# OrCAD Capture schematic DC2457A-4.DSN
size Custom; title: 60V LOW EMI SYNCHRONOUS 4-SWITCH; rev: 4; note: DC2457A
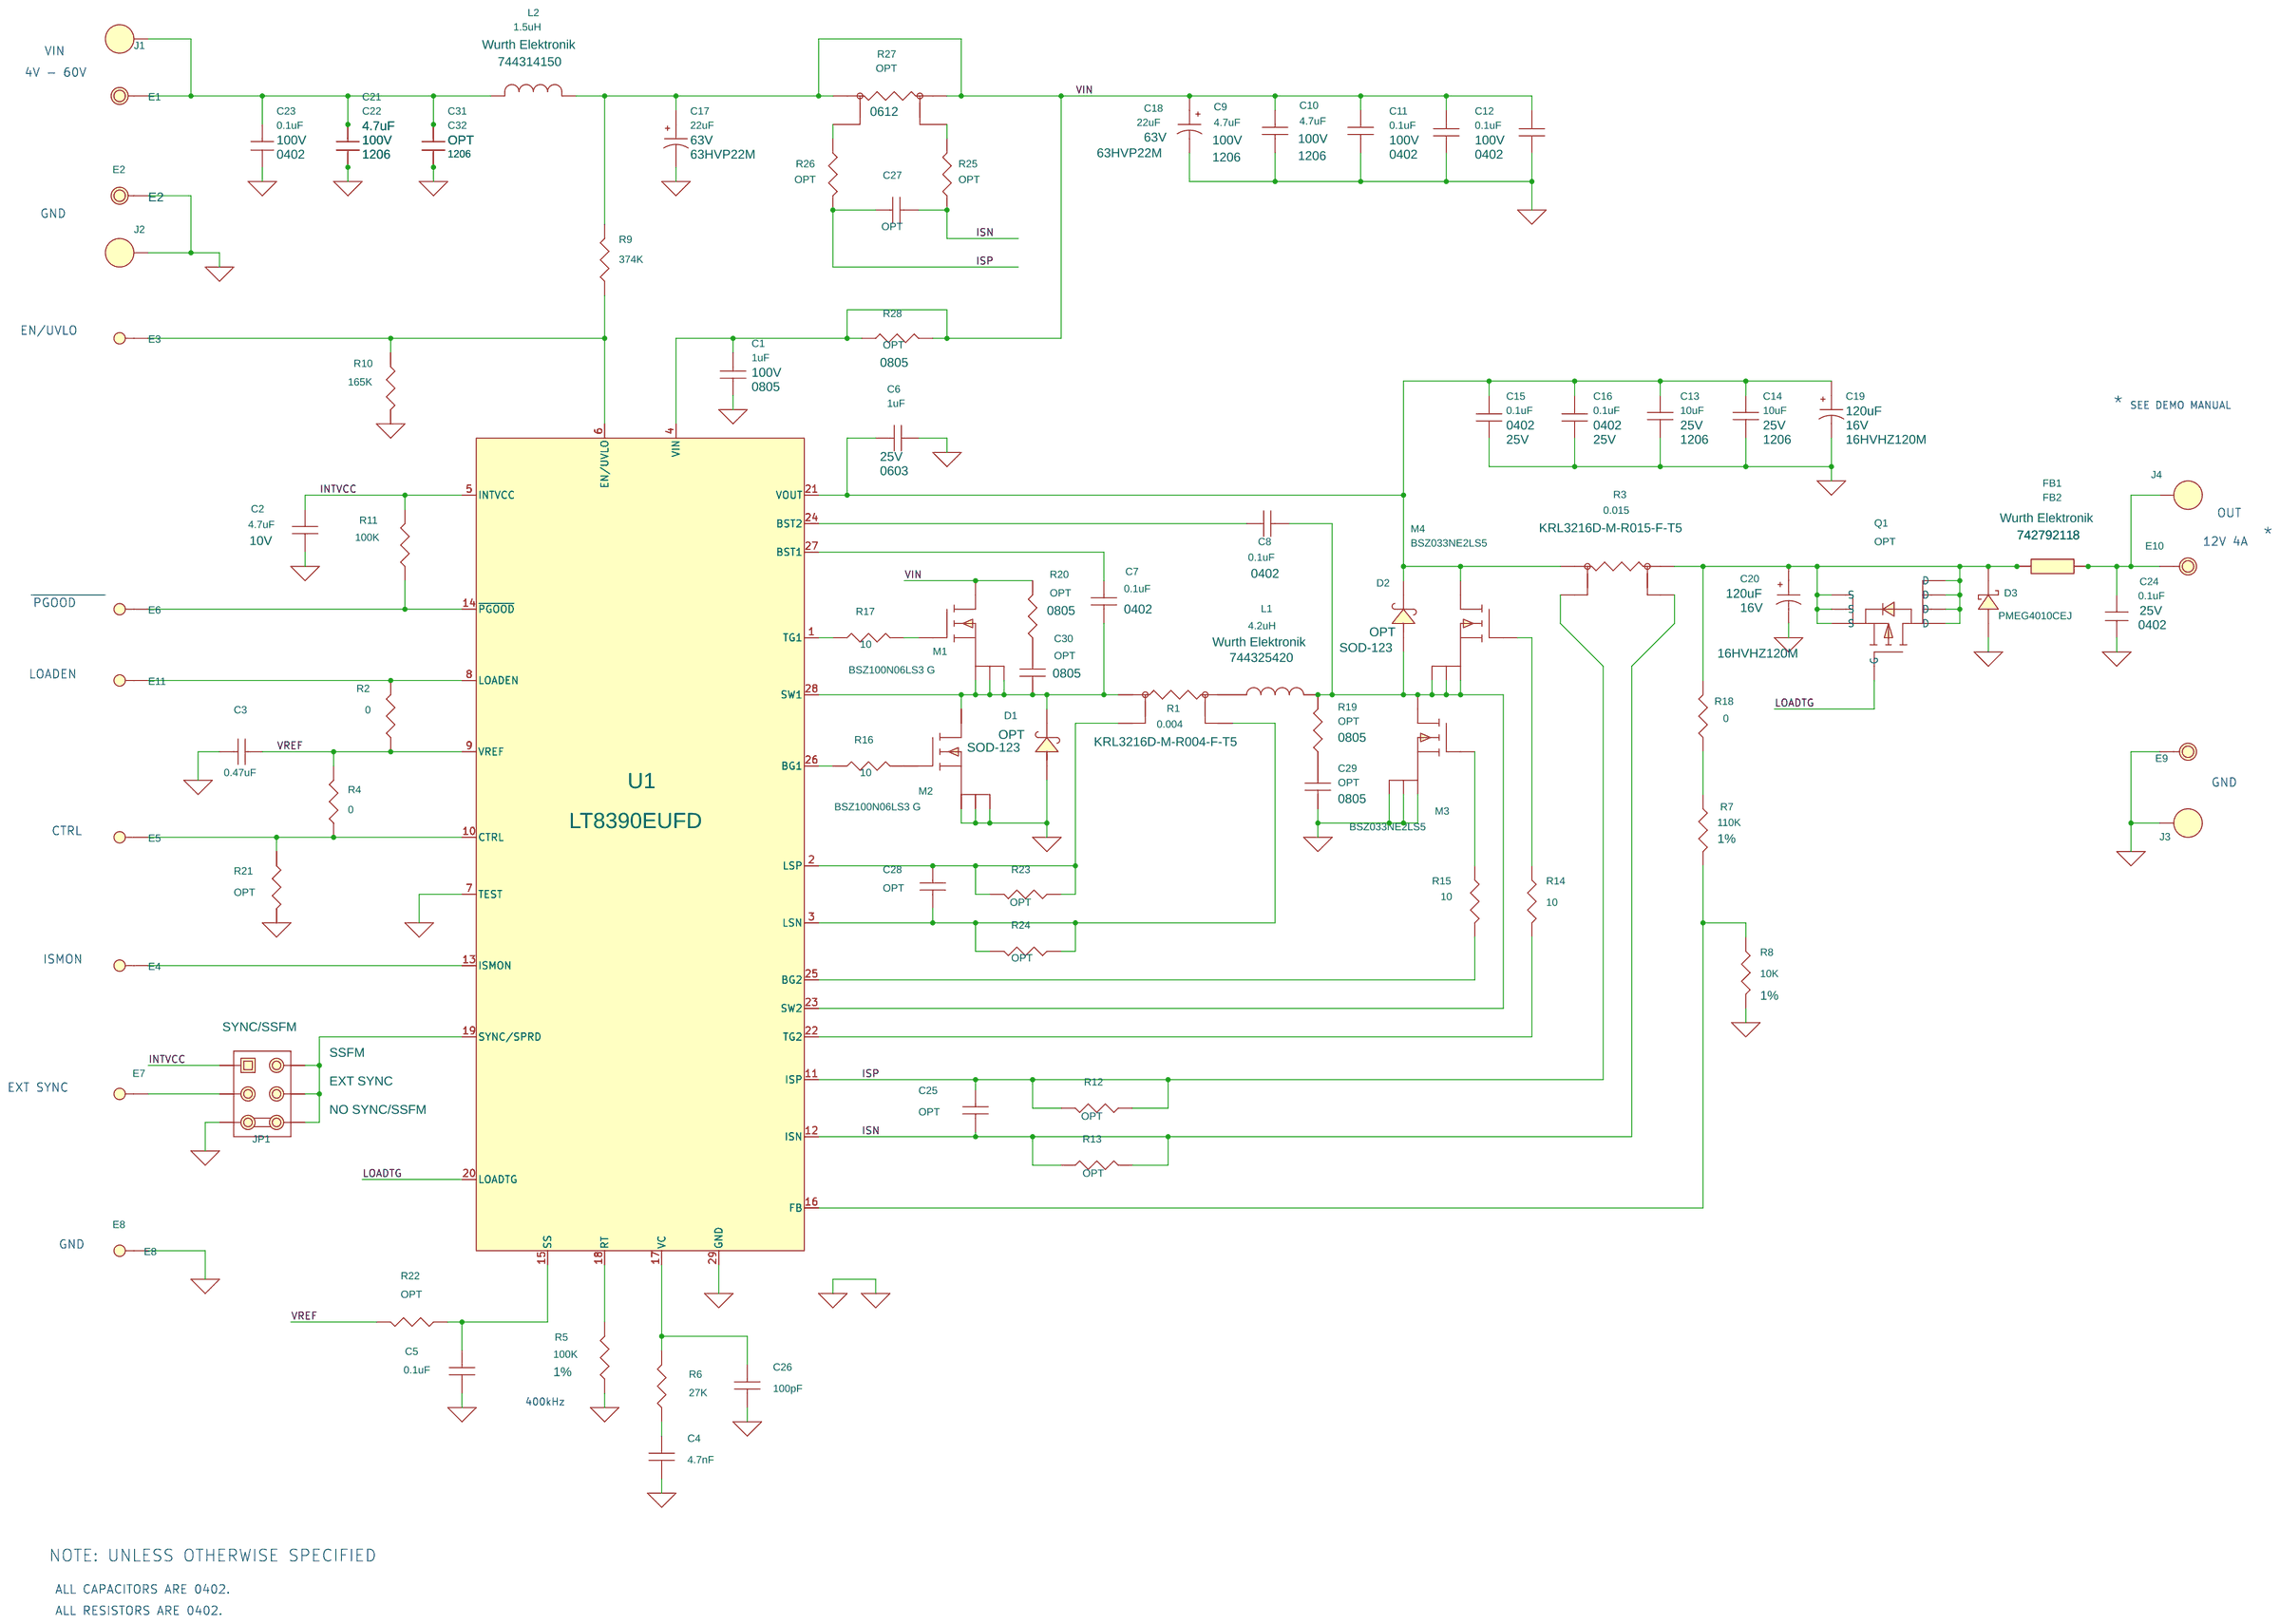
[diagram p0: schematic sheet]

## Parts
C1  1uF  [0805]
C2  4.7uF  [0402]
C3  0.47uF  [0402]
C4  4.7nF  [0402]
C5  0.1uF  [0402]
C6  1uF  [0603]
C7  0.1uF  [0402]
C8  0.1uF  [0402]
C9  4.7uF  [1206]
C10  4.7uF  [1206]
C11  0.1uF  [0402]
C12  0.1uF  [0402]
C13  10uF  [1206]
C14  10uF  [1206]
C15  0.1uF  [0402]
C16  0.1uF  [0402]
C17  22uF  [CAP-CE-8x10.2]
C18  22uF  [CAP-CE-8x10.2]
C19  120uF  [CAP-CE-BS-6.3X7.7]
C20  120uF  [CAP-CE-BS-6.3X7.7]
C21  4.7uF  [1206]
C22  4.7uF  [1206]
C23  0.1uF  [0402]
C24  0.1uF  [0402]
C25  OPT  [0402]
C26  100pF  [0402]
C27  OPT  [0402]
C28  OPT  [0402]
C29  OPT  [0805]
C30  OPT  [0805]
C31  OPT  [1206]
C32  OPT  [1206]
D1  OPT  [SOD-123]
D2  OPT  [SOD-123]
D3  PMEG4010CEJ  [SOD-323F]
E1  Testpoint  [MM/2501]
E2  Testpoint  [MM/2501]
E3  Testpoint  [MM/2308]
E4  Testpoint  [MM/2308]
E5  Testpoint  [MM/2308]
E6  Testpoint  [MM/2308]
E7  Testpoint  [MM/2308]
E8  Testpoint  [MM/2308]
E9  Testpoint  [MM/2501]
E10  Testpoint  [MM/2501]
E11  Testpoint  [MM/2308]
FB1  742792118  [1206]
FB2  742792118  [1206]
J1  BANANA-JACK  [KEY-575-4]
J2  BANANA-JACK  [KEY-575-4]
J3  BANANA-JACK  [KEY-575-4]
J4  BANANA-JACK  [KEY-575-4]
JP1  3 Pins 2mm Ctrs.  [JP3X2/079]
L1  4.2uH  [IND-744325]
L2  1.5uH  [IND-744314]
M1  BSZ100N06LS3 G  [POWERPAK-1212-8-S-5P]
M2  BSZ100N06LS3 G  [POWERPAK-1212-8-S-5P]
M3  BSZ033NE2LS5  [POWERPAK-1212-8-S-5P]
M4  BSZ033NE2LS5  [POWERPAK-1212-8-S-5P]
Q1  OPT  [POWERPAK-1212-8-S]
R1  0.004  [0612]
R2  0  [0402]
R3  0.015  [0612]
R4  0  [0402]
R5  100K  [0402]
R6  27K  [0402]
R7  110K  [0402]
R8  10K  [0402]
R9  374K  [0402]
R10  165K  [0402]
R11  100K  [0402]
R12  OPT  [0402]
R13  OPT  [0402]
R14  10  [0402]
R15  10  [0402]
R16  10  [0402]
R17  10  [0402]
R18  0  [0402]
R19  OPT  [0805]
R20  OPT  [0805]
R21  OPT  [0402]
R22  OPT  [0402]
R23  OPT  [0402]
R24  OPT  [0402]
R25  OPT  [0402]
R26  OPT  [0402]
R27  OPT  [0612]
R28  OPT  [0805]
U1  LT8390EUFD  [QFN-28-4X5]
XJP1  2mm Ctrs.

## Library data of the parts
C1 = CAP_NP: 1st Part Field: V; 4th Part Field: MF; 7th Part Field: CAP.,; Voltage: 100V
C2 = CAP_NP: 1st Part Field: V; 4th Part Field: MF; 7th Part Field: CAP.,; Voltage: 10V
C3-C5 C7 C8 C25-C29 = CAP_NP: 1st Part Field: V; 4th Part Field: MF; 7th Part Field: CAP.,; Voltage: 6.3V
C6 = CAP_NP: 1st Part Field: V; 4th Part Field: MF; 7th Part Field: CAP.,; Voltage: 25V
C9-C12 = CAP_NP: 1st Part Field: 100V; 4th Part Field: MF; 7th Part Field: CAP.,; Voltage: 100V
C13-C16 = CAP_NP: 1st Part Field: 25V; 4th Part Field: MF; 7th Part Field: CAP.,; Voltage: 25V
C17 C18 = 16TQC47M: 1st Part Field: 63V; 2nd Part Field: 20%; 4th Part Field: SUN ELEC.; 5th Part Field: 63HVP22M; 7th Part Field: CAP.,
C19 C20 = 16TQC47M: 1st Part Field: 16V; 2nd Part Field: 20%; 4th Part Field: SUN ELEC.; 5th Part Field: 16HVHZ120M; 7th Part Field: CAP.,
C21-C23 = CAP0603: 1ST PART FIELD: 100V; Voltage: 100V
C24 = CAP0603: 1ST PART FIELD: 25V; Voltage: 25V
C30 = CAP_NP: 1st Part Field: V; 4th Part Field: MF / MF / MF; 7th Part Field: CAP.,; Voltage: 6.3V
C31 = CAP0603: 1ST PART FIELD: V; 2ND PART FIELD: % 0603; 3RD PART FIELD: TYPE; 5TH PART FIELD: 0603
C32 = CAP0603
D1 D2 = DIODE_4
D3 = BAT54WS: 1ST PART FIELD: DIODE SCHOTTKY; 4TH PART FIELD: NXP Semiconductors; 5TH PART FIELD: PMEG6010CEJ,115; 7TH PART FIELD: DIODE SCHOTTKY,
E1 E2 E9 E10 = MillMax-2501-2_2: V: GND
E3-E5 E7 E8 E11 = MillMax-2501-2_3: V: GND
E6 = MillMax-2501-2_4: V: GND
FB1 FB2 = C_R: 4th Part Field: Wurth Elektronik; 7th Part Field: BEAD, CHIP,
J1-J4 = BANANA-JACK: 8th Part Field: 4V - 50V; 9th Part Field: PVIN
JP1 = Samtec_TMM-104-02-L-S_9: 10th Part Field: EXT SYNC; 11th Part Field: NO SYNC/SSFM; 13tht Part Field: SYNC/SSFM; 9th Part Field: SSFM
L1 = INDUCTOR: 2nd Part Field: 744325420; 4th Part Field: Wurth Elektronik; 5th Part Field: 744325420; 7th Part Field: INDUCTOR,
L2 = IND_0: 2nd Part Field: 744325330; 4TH PART FIELD: Wurth Elektronik; 5TH PART FIELD: 744314150
M1-M4 = MOS_FET_9
Q1 = Si7423DN: 5TH PART FIELD: Si7415DN
R1 = LRC1206-SENSE_0: 1st Part Field: 1W; 4th Part Field: SUSUMU; 5th Part Field: KRL3216D-M-R004-F-T5; 7th Part Field: RES.,
R2 R4 R6 R9-R21 R23-R26 R28 = RESISTOR: 4th Part Field: MF; 5th Part Field: PART NO; 7th Part Field: RES.,
R3 = LRC1206-SENSE_0: 1st Part Field: 1W; 4th Part Field: SUSUMU; 5th Part Field: KRL3216D-M-R015-F-T5; 7th Part Field: RES.,
R5 R7 R8 = RESISTOR: 2nd Part Field: 1%; 4th Part Field: MF; 5th Part Field: PART NO; 7th Part Field: RES.,
R22 = RESISTOR_1: 4th Part Field: MF; 5th Part Field: PART NO; 7th Part Field: RES.,
R27 = LRC1206-SENSE_0: 7th Part Field: RES.,
U1 = LT3791EFE_39
XJP1 = Samtec_2SN-BK-G_1: 7th Part Field: Shunt,

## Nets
GND: C1.1 C2.2 C3.2 C4.2 C5.2 C6.1 C9.2 C10.2 C11.1 C12.1 C13.2 C14.2 C15.1 C16.1 C17.2 C18.2 C19.2 C20.2 C21.2 C22.2 C23.2 C24.2 C26.2 C29.2 C31.2 C32.2 D1.2 D3.2(A) E2.1 E8.1 E9.1 J2.1 J3.1 JP1.5 M2.1(S) M2.2(S) M2.3(S) M3.1(S) M3.2(S) M3.3(S) R5.2 R8.2 R10.2 R21.2 U1.7(TEST) U1.29(GND)
VIN: C1.2 C9.1 C10.1 C11.2 C12.2 C17.1 C18.1 L2.2 M1.5(D) R9.1 R20.1 R27.1 R27.3 R28.1 R28.2 U1.4(VIN)
INTVCC: C2.1 JP1.1 R11.1 U1.5(INTVCC)
ISN: C25.2 C27.2 R3.2 R13.1 R13.2 R25.1 U1.12(ISN)
ISP: C25.1 C27.1 R3.4 R12.1 R12.2 R26.1 U1.11(ISP)
LOADTG: Q1.4(G) U1.20(LOADTG)
VREF: C3.1 R2.2 R4.2 R22.2 U1.9(VREF)
N16994718: C7.1 U1.27(BST1)
N17009346: C4.1 R6.2
N17200393: C21.1 C22.1 C23.1 C31.1 C32.1 E1.1 J1.1 L2.1
N17395809: E3.1 R9.2 R10.1 U1.6(EN/UVLO)
N17465905: C8.2 D2.2 L1.2 M3.5(D) M4.1(S) M4.2(S) M4.3(S) R19.1 U1.23(SW2)
N17465907: C6.2 C13.1 C14.1 C15.2 C16.2 C19.1 D2.1 M4.5(D) R3.3 U1.21(VOUT)
N17508110: R16.1 U1.26(BG1)
N17509789: R17.1 U1.1(TG1)
N17526148: C28.1 R1.2 R23.1 R23.2 U1.2(LSP)
N17527032: C28.2 R1.4 R24.1 R24.2 U1.3(LSN)
N17680754: C7.2 C30.2 D1.1 M1.1(S) M1.2(S) M1.3(S) M2.5(D) R1.1 U1.28(SW1)
N17708049: C24.1 E10.1 FB1.1 FB2.1 J4.1
N17718651: M4.4(G) R14.1
N17732267: C8.1 U1.24(BST2)
N17841959: E6.1 R11.2 U1.14(~{PGOOD})
N17844598: E4.1 U1.13(ISMON)
N17844661: JP1.2 JP1.4 JP1.6 U1.19(SYNC/SPRD)
N17844682: E7.1 JP1.3
N17845406: C5.1 R22.1 U1.15(SS)
N17868485: C26.1 R6.1 U1.17(VC)
N17869628: R7.2 R8.1 U1.16(FB)
N17869644: C20.1 D3.1(K) FB1.2 FB2.2 Q1.1(S) Q1.2(S) Q1.3(S) Q1.5(D) Q1.6(D) Q1.7(D) Q1.8(D) R3.1 R18.1
N17869668: R7.1 R18.2
N17925585: E5.1 R4.1 R21.1 U1.10(CTRL)
N17926399: E11.1 R2.1 U1.8(LOADEN)
N17936306: M3.4(G) R15.1
N18006993: M1.4(G) R17.2
N18008210: R25.2 R27.2
N18008211: R26.2 R27.4
N18014026: M2.4(G) R16.2
N18024921: L1.1 R1.3
N18034669: C29.1 R19.2
N18034670: C30.1 R20.2
N18377159: R15.2 U1.25(BG2)
N18382365: R14.2 U1.22(TG2)
N18452641: R5.1 U1.18(RT)

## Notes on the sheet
- VIN
- 4V - 60V
- GND
- EN/UVLO
- *
- SEE DEMO MANUAL
- OUT
- 12V 4A
- *
- PGOOD
- LOADEN
- GND
- CTRL
- ISMON
- EXT SYNC
- GND
- 400kHz
- NOTE: UNLESS OTHERWISE SPECIFIED
- ALL CAPACITORS ARE 0402.
- ALL RESISTORS ARE 0402.
